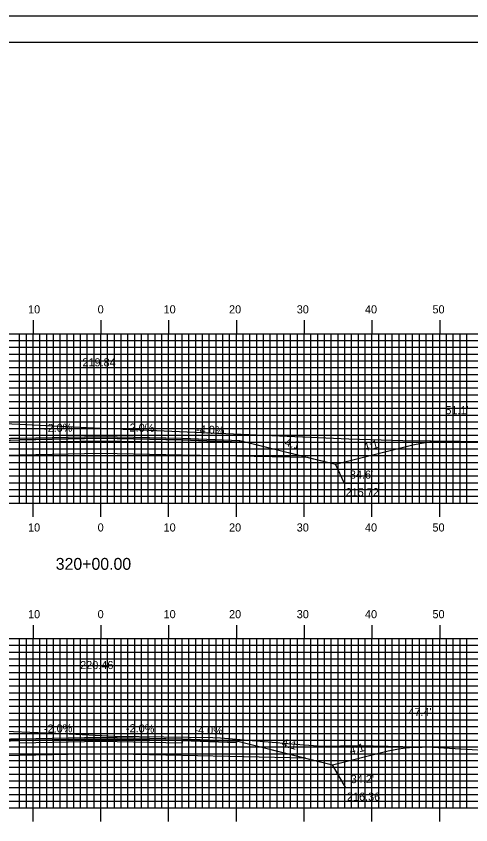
# Model space of a CAD drawing. Extents: x 1820031 to 1820374, y 442591 to 442811.
# Drawn here: x 1820184.2 to 1820251.3, y 442691.2 to 442810.5 of the extents above; entities that cross this region are included whole.
import ezdxf

# ---------------------------------------------------------------- set-up
doc = ezdxf.new("R2010")
doc.units = 0
for name, color, linetype in [('ANNOTATION', 7, 'Continuous'), ('BORDER', 7, 'Continuous'), ('D_Roadway_Centerline', 7, 'Continuous'), ('D_Roadway_Centerline_Text', 7, 'Continuous'), ('D_Roadway_Edge_Shoulder', 7, 'Continuous'), ('D_Roadway_Edge_TW', 7, 'Continuous'), ('D_Roadway_Pavement', 7, 'Continuous'), ('D_Roadway_SlopeLines', 7, 'Continuous'), ('D_Roadway_SubGrade', 7, 'Continuous'), ('D_Text_Standard', 7, 'Continuous'), ('H_V ANNOTATION', 7, 'Continuous'), ('MAJOR', 7, 'Continuous'), ('MINOR', 7, 'Continuous'), ('PLOT BOUNDARY', 7, 'Continuous'), ('S_Roadway_Centerline', 7, 'Continuous')]:
    doc.layers.add(name, color=color, linetype=linetype)

msp = doc.modelspace()

# ---------------------------------------------------------------- linework, layer by layer
at = {"layer": 'ANNOTATION'}
for points in [[(1820238.32, 442741.55), (1820232.63, 442741.55), (1820231.3, 442744.39)], [(1820238.52, 442696.61), (1820232.83, 442696.61), (1820230.86, 442700.02)]]:
    msp.add_lwpolyline(points, dxfattribs=at)
at = {"layer": 'BORDER'}
msp.add_lwpolyline([(1820047.09, 442596.67), (1820367.09, 442596.67), (1820367.09, 442806.67), (1820047.09, 442806.67)], close=True, dxfattribs=at)
at = {"layer": 'D_Roadway_Centerline'}
for points in [[(1820131.25, 442751.74), (1820132.5, 442751.64), (1820133.75, 442751.47), (1820135, 442751.25), (1820136.25, 442750.96), (1820162.52, 442744.4), (1820166.52, 442745.4), (1820176.69, 442747.94), (1820184.69, 442748.26), (1820196.69, 442748.5), (1820208.69, 442748.26), (1820217.17, 442747.92), (1820227.3, 442745.39), (1820231.3, 442744.39), (1820242.74, 442747.25), (1820243.99, 442747.52), (1820245.24, 442747.71), (1820246.49, 442747.82), (1820247.74, 442747.85)], [(1820132.17, 442707.01), (1820133.42, 442706.96), (1820134.67, 442706.83), (1820135.92, 442706.63), (1820137.17, 442706.36), (1820162.52, 442700.02), (1820166.52, 442701.02), (1820176.69, 442703.57), (1820184.69, 442703.89), (1820196.69, 442704.13), (1820208.69, 442703.89), (1820216.69, 442703.57), (1820226.86, 442701.02), (1820230.86, 442700.02), (1820239.1, 442702.08), (1820240.35, 442702.35), (1820241.6, 442702.54), (1820242.85, 442702.64), (1820244.1, 442702.65)]]:
    msp.add_lwpolyline(points, dxfattribs=at)
at = {"layer": 'D_Roadway_Edge_Shoulder'}
for points in [[(1820184.69, 442748.26), (1820176.69, 442747.94), (1820176.69, 442747.69), (1820184.69, 442748.01)], [(1820208.69, 442748.26), (1820217.17, 442747.92), (1820217.17, 442747.67), (1820208.69, 442748.01)], [(1820184.69, 442703.89), (1820176.69, 442703.57), (1820176.69, 442703.32), (1820184.69, 442703.64)], [(1820208.69, 442703.89), (1820216.69, 442703.57), (1820216.69, 442703.32), (1820208.69, 442703.64)]]:
    msp.add_lwpolyline(points, close=True, dxfattribs=at)
at = {"layer": 'D_Roadway_Edge_TW'}
for points in [[(1820184.69, 442748.01), (1820184.69, 442748.26), (1820196.69, 442748.5), (1820208.69, 442748.26), (1820208.69, 442748.01), (1820196.69, 442748.25)], [(1820184.69, 442703.64), (1820184.69, 442703.89), (1820196.69, 442704.13), (1820208.69, 442703.89), (1820208.69, 442703.64), (1820196.69, 442703.88)]]:
    msp.add_lwpolyline(points, close=True, dxfattribs=at)
at = {"layer": 'D_Roadway_Pavement'}
for points in [[(1820184.69, 442747.59), (1820184.69, 442748.01), (1820196.69, 442748.25), (1820208.69, 442748.01), (1820208.69, 442747.59), (1820196.69, 442747.83)], [(1820184.69, 442703.22), (1820184.69, 442703.64), (1820196.69, 442703.88), (1820208.69, 442703.64), (1820208.69, 442703.22), (1820196.69, 442703.46)]]:
    msp.add_lwpolyline(points, close=True, dxfattribs=at)
at = {"layer": 'D_Roadway_SlopeLines'}
for points in [[(1820217.17, 442747.92), (1820231.3, 442744.39)], [(1820231.3, 442744.39), (1820242.74, 442747.25), (1820243.99, 442747.52), (1820245.24, 442747.71), (1820246.49, 442747.82), (1820247.74, 442747.85)], [(1820216.69, 442703.57), (1820230.86, 442700.02)], [(1820230.86, 442700.02), (1820239.1, 442702.08), (1820240.35, 442702.35), (1820241.6, 442702.54), (1820242.85, 442702.64), (1820244.1, 442702.65)]]:
    msp.add_lwpolyline(points, dxfattribs=at)
at = {"layer": 'D_Roadway_SubGrade'}
for points in [[(1820184.69, 442745.76), (1820166.52, 442745.4), (1820176.69, 442747.94), (1820176.69, 442747.69), (1820184.69, 442748.01), (1820196.69, 442748.25), (1820208.69, 442748.01), (1820217.17, 442747.67), (1820217.17, 442747.92), (1820227.3, 442745.39), (1820208.69, 442745.76), (1820196.69, 442746)], [(1820184.69, 442701.39), (1820166.52, 442701.02), (1820176.69, 442703.57), (1820176.69, 442703.32), (1820184.69, 442703.64), (1820196.69, 442703.88), (1820208.69, 442703.64), (1820216.69, 442703.32), (1820216.69, 442703.57), (1820226.86, 442701.02), (1820208.69, 442701.39), (1820196.69, 442701.63)]]:
    msp.add_lwpolyline(points, close=True, dxfattribs=at)
at = {"layer": 'MAJOR'}
for p, q in [((1820186.69, 442765.67), (1820186.69, 442763.67)), ((1820196.69, 442765.67), (1820196.69, 442763.67)), ((1820206.69, 442765.67), (1820206.69, 442763.67)), ((1820216.69, 442765.67), (1820216.69, 442763.67)), ((1820226.69, 442765.67), (1820226.69, 442763.67)), ((1820236.69, 442765.67), (1820236.69, 442763.67)), ((1820246.69, 442765.67), (1820246.69, 442763.67)), ((1820056.69, 442763.67), (1820336.69, 442763.67)), ((1820056.69, 442763.67), (1820336.69, 442763.67)), ((1820186.69, 442738.67), (1820186.69, 442763.67)), ((1820196.69, 442738.67), (1820196.69, 442763.67)), ((1820206.69, 442738.67), (1820206.69, 442763.67)), ((1820216.69, 442738.67), (1820216.69, 442763.67)), ((1820226.69, 442738.67), (1820226.69, 442763.67)), ((1820236.69, 442738.67), (1820236.69, 442763.67)), ((1820246.69, 442738.67), (1820246.69, 442763.67)), ((1820056.69, 442758.67), (1820336.69, 442758.67)), ((1820056.69, 442753.67), (1820336.69, 442753.67)), ((1820056.69, 442748.67), (1820336.69, 442748.67)), ((1820056.69, 442743.67), (1820336.69, 442743.67)), ((1820056.69, 442738.67), (1820336.69, 442738.67)), ((1820056.69, 442738.67), (1820336.69, 442738.67)), ((1820186.69, 442736.66), (1820186.69, 442738.67)), ((1820196.69, 442736.66), (1820196.69, 442738.67)), ((1820206.69, 442736.66), (1820206.69, 442738.67)), ((1820216.69, 442736.66), (1820216.69, 442738.67)), ((1820226.69, 442736.66), (1820226.69, 442738.67)), ((1820236.69, 442736.66), (1820236.69, 442738.67)), ((1820246.69, 442736.66), (1820246.69, 442738.67)), ((1820186.69, 442720.67), (1820186.69, 442718.67)), ((1820196.69, 442720.67), (1820196.69, 442718.67)), ((1820206.69, 442720.67), (1820206.69, 442718.67)), ((1820216.69, 442720.67), (1820216.69, 442718.67)), ((1820226.69, 442720.67), (1820226.69, 442718.67)), ((1820236.69, 442720.67), (1820236.69, 442718.67)), ((1820246.69, 442720.67), (1820246.69, 442718.67)), ((1820056.69, 442718.67), (1820336.69, 442718.67)), ((1820056.69, 442718.67), (1820336.69, 442718.67)), ((1820186.69, 442693.67), (1820186.69, 442718.67)), ((1820196.69, 442693.67), (1820196.69, 442718.67)), ((1820206.69, 442693.67), (1820206.69, 442718.67)), ((1820216.69, 442693.67), (1820216.69, 442718.67)), ((1820226.69, 442693.67), (1820226.69, 442718.67)), ((1820236.69, 442693.67), (1820236.69, 442718.67)), ((1820246.69, 442693.67), (1820246.69, 442718.67)), ((1820056.69, 442713.67), (1820336.69, 442713.67)), ((1820056.69, 442708.67), (1820336.69, 442708.67)), ((1820056.69, 442703.67), (1820336.69, 442703.67)), ((1820056.69, 442698.67), (1820336.69, 442698.67)), ((1820056.69, 442693.67), (1820336.69, 442693.67)), ((1820056.69, 442693.67), (1820336.69, 442693.67)), ((1820186.69, 442691.66), (1820186.69, 442693.67)), ((1820196.69, 442691.66), (1820196.69, 442693.67)), ((1820206.69, 442691.66), (1820206.69, 442693.67)), ((1820216.69, 442691.66), (1820216.69, 442693.67)), ((1820226.69, 442691.66), (1820226.69, 442693.67)), ((1820236.69, 442691.66), (1820236.69, 442693.67)), ((1820246.69, 442691.66), (1820246.69, 442693.67))]:
    msp.add_line(p, q, dxfattribs=at)
at = {"layer": 'MINOR'}
for p, q in [((1820184.69, 442738.67), (1820184.69, 442763.67)), ((1820185.69, 442738.67), (1820185.69, 442763.67)), ((1820187.69, 442738.67), (1820187.69, 442763.67)), ((1820188.69, 442738.67), (1820188.69, 442763.67)), ((1820189.69, 442738.67), (1820189.69, 442763.67)), ((1820190.69, 442738.67), (1820190.69, 442763.67)), ((1820191.69, 442738.67), (1820191.69, 442763.67)), ((1820192.69, 442738.67), (1820192.69, 442763.67)), ((1820193.69, 442738.67), (1820193.69, 442763.67)), ((1820194.69, 442738.67), (1820194.69, 442763.67)), ((1820195.69, 442738.67), (1820195.69, 442763.67)), ((1820197.69, 442738.67), (1820197.69, 442763.67)), ((1820198.69, 442738.67), (1820198.69, 442763.67)), ((1820199.69, 442738.67), (1820199.69, 442763.67)), ((1820200.69, 442738.67), (1820200.69, 442763.67)), ((1820201.69, 442738.67), (1820201.69, 442763.67)), ((1820202.69, 442738.67), (1820202.69, 442763.67)), ((1820203.69, 442738.67), (1820203.69, 442763.67)), ((1820204.69, 442738.67), (1820204.69, 442763.67)), ((1820205.69, 442738.67), (1820205.69, 442763.67)), ((1820207.69, 442738.67), (1820207.69, 442763.67)), ((1820208.69, 442738.67), (1820208.69, 442763.67)), ((1820209.69, 442738.67), (1820209.69, 442763.67)), ((1820210.69, 442738.67), (1820210.69, 442763.67)), ((1820211.69, 442738.67), (1820211.69, 442763.67)), ((1820212.69, 442738.67), (1820212.69, 442763.67)), ((1820213.69, 442738.67), (1820213.69, 442763.67)), ((1820214.69, 442738.67), (1820214.69, 442763.67)), ((1820215.69, 442738.67), (1820215.69, 442763.67)), ((1820217.69, 442738.67), (1820217.69, 442763.67)), ((1820218.69, 442738.67), (1820218.69, 442763.67)), ((1820219.69, 442738.67), (1820219.69, 442763.67)), ((1820220.69, 442738.67), (1820220.69, 442763.67)), ((1820221.69, 442738.67), (1820221.69, 442763.67)), ((1820222.69, 442738.67), (1820222.69, 442763.67)), ((1820223.69, 442738.67), (1820223.69, 442763.67)), ((1820224.69, 442738.67), (1820224.69, 442763.67)), ((1820225.69, 442738.67), (1820225.69, 442763.67)), ((1820227.69, 442738.67), (1820227.69, 442763.67)), ((1820228.69, 442738.67), (1820228.69, 442763.67)), ((1820229.69, 442738.67), (1820229.69, 442763.67)), ((1820230.69, 442738.67), (1820230.69, 442763.67)), ((1820231.69, 442738.67), (1820231.69, 442763.67)), ((1820232.69, 442738.67), (1820232.69, 442763.67)), ((1820233.69, 442738.67), (1820233.69, 442763.67)), ((1820234.69, 442738.67), (1820234.69, 442763.67)), ((1820235.69, 442738.67), (1820235.69, 442763.67)), ((1820237.69, 442738.67), (1820237.69, 442763.67)), ((1820238.69, 442738.67), (1820238.69, 442763.67)), ((1820239.69, 442738.67), (1820239.69, 442763.67)), ((1820240.69, 442738.67), (1820240.69, 442763.67)), ((1820241.69, 442738.67), (1820241.69, 442763.67)), ((1820242.69, 442738.67), (1820242.69, 442763.67)), ((1820243.69, 442738.67), (1820243.69, 442763.67)), ((1820244.69, 442738.67), (1820244.69, 442763.67)), ((1820245.69, 442738.67), (1820245.69, 442763.67)), ((1820247.69, 442738.67), (1820247.69, 442763.67)), ((1820248.69, 442738.67), (1820248.69, 442763.67)), ((1820249.69, 442738.67), (1820249.69, 442763.67)), ((1820250.69, 442738.67), (1820250.69, 442763.67)), ((1820056.69, 442762.67), (1820336.69, 442762.67)), ((1820056.69, 442761.67), (1820336.69, 442761.67)), ((1820056.69, 442760.67), (1820336.69, 442760.67)), ((1820056.69, 442759.67), (1820336.69, 442759.67)), ((1820056.69, 442757.67), (1820336.69, 442757.67)), ((1820056.69, 442756.67), (1820336.69, 442756.67)), ((1820056.69, 442755.67), (1820336.69, 442755.67)), ((1820056.69, 442754.67), (1820336.69, 442754.67)), ((1820056.69, 442752.67), (1820336.69, 442752.67)), ((1820056.69, 442751.67), (1820336.69, 442751.67)), ((1820056.69, 442750.67), (1820336.69, 442750.67)), ((1820056.69, 442749.67), (1820336.69, 442749.67)), ((1820056.69, 442747.67), (1820336.69, 442747.67)), ((1820056.69, 442746.67), (1820336.69, 442746.67)), ((1820056.69, 442745.67), (1820336.69, 442745.67)), ((1820056.69, 442744.67), (1820336.69, 442744.67)), ((1820056.69, 442742.67), (1820336.69, 442742.67)), ((1820056.69, 442741.67), (1820336.69, 442741.67)), ((1820056.69, 442740.67), (1820336.69, 442740.67)), ((1820056.69, 442739.67), (1820336.69, 442739.67)), ((1820184.69, 442693.67), (1820184.69, 442718.67)), ((1820185.69, 442693.67), (1820185.69, 442718.67)), ((1820187.69, 442693.67), (1820187.69, 442718.67)), ((1820188.69, 442693.67), (1820188.69, 442718.67)), ((1820189.69, 442693.67), (1820189.69, 442718.67)), ((1820190.69, 442693.67), (1820190.69, 442718.67)), ((1820191.69, 442693.67), (1820191.69, 442718.67)), ((1820192.69, 442693.67), (1820192.69, 442718.67)), ((1820193.69, 442693.67), (1820193.69, 442718.67)), ((1820194.69, 442693.67), (1820194.69, 442718.67)), ((1820195.69, 442693.67), (1820195.69, 442718.67)), ((1820197.69, 442693.67), (1820197.69, 442718.67)), ((1820198.69, 442693.67), (1820198.69, 442718.67)), ((1820199.69, 442693.67), (1820199.69, 442718.67)), ((1820200.69, 442693.67), (1820200.69, 442718.67)), ((1820201.69, 442693.67), (1820201.69, 442718.67)), ((1820202.69, 442693.67), (1820202.69, 442718.67)), ((1820203.69, 442693.67), (1820203.69, 442718.67)), ((1820204.69, 442693.67), (1820204.69, 442718.67)), ((1820205.69, 442693.67), (1820205.69, 442718.67)), ((1820207.69, 442693.67), (1820207.69, 442718.67)), ((1820208.69, 442693.67), (1820208.69, 442718.67)), ((1820209.69, 442693.67), (1820209.69, 442718.67)), ((1820210.69, 442693.67), (1820210.69, 442718.67)), ((1820211.69, 442693.67), (1820211.69, 442718.67)), ((1820212.69, 442693.67), (1820212.69, 442718.67)), ((1820213.69, 442693.67), (1820213.69, 442718.67)), ((1820214.69, 442693.67), (1820214.69, 442718.67)), ((1820215.69, 442693.67), (1820215.69, 442718.67)), ((1820217.69, 442693.67), (1820217.69, 442718.67)), ((1820218.69, 442693.67), (1820218.69, 442718.67)), ((1820219.69, 442693.67), (1820219.69, 442718.67)), ((1820220.69, 442693.67), (1820220.69, 442718.67)), ((1820221.69, 442693.67), (1820221.69, 442718.67)), ((1820222.69, 442693.67), (1820222.69, 442718.67)), ((1820223.69, 442693.67), (1820223.69, 442718.67)), ((1820224.69, 442693.67), (1820224.69, 442718.67)), ((1820225.69, 442693.67), (1820225.69, 442718.67)), ((1820227.69, 442693.67), (1820227.69, 442718.67)), ((1820228.69, 442693.67), (1820228.69, 442718.67)), ((1820229.69, 442693.67), (1820229.69, 442718.67)), ((1820230.69, 442693.67), (1820230.69, 442718.67)), ((1820231.69, 442693.67), (1820231.69, 442718.67)), ((1820232.69, 442693.67), (1820232.69, 442718.67)), ((1820233.69, 442693.67), (1820233.69, 442718.67)), ((1820234.69, 442693.67), (1820234.69, 442718.67)), ((1820235.69, 442693.67), (1820235.69, 442718.67)), ((1820237.69, 442693.67), (1820237.69, 442718.67)), ((1820238.69, 442693.67), (1820238.69, 442718.67)), ((1820239.69, 442693.67), (1820239.69, 442718.67)), ((1820240.69, 442693.67), (1820240.69, 442718.67)), ((1820241.69, 442693.67), (1820241.69, 442718.67)), ((1820242.69, 442693.67), (1820242.69, 442718.67)), ((1820243.69, 442693.67), (1820243.69, 442718.67)), ((1820244.69, 442693.67), (1820244.69, 442718.67)), ((1820245.69, 442693.67), (1820245.69, 442718.67)), ((1820247.69, 442693.67), (1820247.69, 442718.67)), ((1820248.69, 442693.67), (1820248.69, 442718.67)), ((1820249.69, 442693.67), (1820249.69, 442718.67)), ((1820250.69, 442693.67), (1820250.69, 442718.67)), ((1820056.69, 442717.67), (1820336.69, 442717.67)), ((1820056.69, 442716.67), (1820336.69, 442716.67)), ((1820056.69, 442715.67), (1820336.69, 442715.67)), ((1820056.69, 442714.67), (1820336.69, 442714.67)), ((1820056.69, 442712.67), (1820336.69, 442712.67)), ((1820056.69, 442711.67), (1820336.69, 442711.67)), ((1820056.69, 442710.67), (1820336.69, 442710.67)), ((1820056.69, 442709.67), (1820336.69, 442709.67)), ((1820056.69, 442707.67), (1820336.69, 442707.67)), ((1820056.69, 442706.67), (1820336.69, 442706.67)), ((1820056.69, 442705.67), (1820336.69, 442705.67)), ((1820056.69, 442704.67), (1820336.69, 442704.67)), ((1820056.69, 442702.67), (1820336.69, 442702.67)), ((1820056.69, 442701.67), (1820336.69, 442701.67)), ((1820056.69, 442700.67), (1820336.69, 442700.67)), ((1820056.69, 442699.67), (1820336.69, 442699.67)), ((1820056.69, 442697.67), (1820336.69, 442697.67)), ((1820056.69, 442696.67), (1820336.69, 442696.67)), ((1820056.69, 442695.67), (1820336.69, 442695.67)), ((1820056.69, 442694.67), (1820336.69, 442694.67))]:
    msp.add_line(p, q, dxfattribs=at)
at = {"layer": 'PLOT BOUNDARY'}
msp.add_lwpolyline([(1820030.9, 442590.55), (1820370.9, 442590.55), (1820370.9, 442810.55), (1820030.9, 442810.55)], close=True, dxfattribs=at)
at = {"layer": 'S_Roadway_Centerline'}
for points in [[(1820056.69, 442754.46), (1820062.03, 442754.36), (1820063.89, 442754.33), (1820065.67, 442754.29), (1820069.06, 442754.43), (1820098.12, 442753.95), (1820113.68, 442752.8), (1820132.79, 442751.65), (1820134.29, 442751.55), (1820140.62, 442751.49), (1820149.41, 442751.38), (1820151.92, 442751.32), (1820165.5, 442751.36), (1820174.38, 442750.71), (1820182.55, 442750.44), (1820197.57, 442749.67), (1820199.21, 442749.66), (1820199.99, 442749.57), (1820203.77, 442749.42), (1820233.29, 442748.15), (1820241.27, 442747.91), (1820249.59, 442747.83), (1820279.36, 442747.36)], [(1820121.31, 442707.11), (1820141.91, 442706.91), (1820145.18, 442706.93), (1820145.84, 442706.89), (1820147.82, 442706.7), (1820160.86, 442705.56), (1820172, 442705.45), (1820178.86, 442705.14), (1820191.06, 442704.67), (1820195.84, 442704.41), (1820198.73, 442704.26), (1820213.19, 442704.07), (1820214.34, 442704), (1820226.03, 442703.01), (1820229.41, 442702.78), (1820234.68, 442702.86), (1820245.62, 442702.62), (1820258.95, 442701.86)]]:
    msp.add_lwpolyline(points, dxfattribs=at)

# ---------------------------------------------------------------- texts
at = {"layer": 'ANNOTATION'}
for s, rotation, p in [('-2.0%', 1.1458, (1820188.3, 442749.13)), ('-2.0%', 358.8542, (1820200.38, 442749.23)), ('-4.0%', 357.7094, (1820210.72, 442748.98)), ('4:1', 345.9638, (1820223.74, 442747.14)), ('4:1', 14.0362, (1820235.56, 442746.31)), ('-2.0%', 1.1458, (1820188.3, 442704.76)), ('-2.0%', 358.8542, (1820200.38, 442704.85)), ('-4.0%', 357.7094, (1820210.48, 442704.62)), ('4:1', 345.9638, (1820223.28, 442702.78)), ('4:1', 14.0362, (1820233.52, 442701.55))]:
    msp.add_text(s, height=1.2, rotation=rotation, dxfattribs=at).set_placement(p)
for s, p in [("34.6'", (1820233.43, 442742.27)), ('215.72', (1820232.8, 442739.67)), ("34.2'", (1820233.56, 442697.33)), ('216.36', (1820233, 442694.73))]:
    msp.add_text(s, height=1.2, dxfattribs=at).set_placement(p)
at = {"layer": 'D_Roadway_Centerline'}
for s, p in [('C', (1820196.69, 442748.5)), ('L', (1820196.69, 442748.49)), ('C', (1820196.69, 442704.13)), ('L', (1820196.69, 442704.12))]:
    msp.add_text(s, height=0.0146, dxfattribs=at).set_placement(p)
at = {"layer": 'D_Roadway_Centerline_Text'}
for s, p in [('219.84', (1820193.97, 442758.85)), ('220.46', (1820193.63, 442714.16))]:
    msp.add_text(s, height=1.2, dxfattribs=at).set_placement(p)
at = {"layer": 'D_Text_Standard'}
for s, p in [("51.1'", (1820247.52, 442751.79)), ("47.4'", (1820242.06, 442707.24))]:
    msp.add_text(s, height=1.2, dxfattribs=at).set_placement(p)
at = {"layer": 'H_V ANNOTATION'}
for s, height, p in [('10', 1.2, (1820185.94, 442766.67)), ('0', 1.2, (1820196.21, 442766.67)), ('10', 1.2, (1820205.94, 442766.67)), ('20', 1.2, (1820215.6, 442766.67)), ('30', 1.2, (1820225.59, 442766.67)), ('40', 1.2, (1820235.66, 442766.67)), ('50', 1.2, (1820245.62, 442766.67)), ('10', 1.2, (1820185.94, 442734.47)), ('0', 1.2, (1820196.21, 442734.47)), ('10', 1.2, (1820205.94, 442734.47)), ('20', 1.2, (1820215.6, 442734.47)), ('30', 1.2, (1820225.59, 442734.47)), ('40', 1.2, (1820235.66, 442734.47)), ('50', 1.2, (1820245.62, 442734.47)), ('320+00.00', 1.75, (1820190.03, 442728.82)), ('10', 1.2, (1820185.94, 442721.67)), ('0', 1.2, (1820196.21, 442721.67)), ('10', 1.2, (1820205.94, 442721.67)), ('20', 1.2, (1820215.6, 442721.67)), ('30', 1.2, (1820225.59, 442721.67)), ('40', 1.2, (1820235.66, 442721.67)), ('50', 1.2, (1820245.62, 442721.67))]:
    msp.add_text(s, height=height, dxfattribs=at).set_placement(p)

doc.saveas('drawing.dxf')
